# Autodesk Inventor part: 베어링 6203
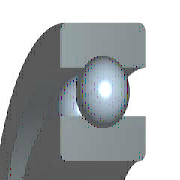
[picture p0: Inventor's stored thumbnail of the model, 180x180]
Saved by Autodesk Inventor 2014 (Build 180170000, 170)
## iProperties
IsCustomPart: 0
Created: 2009-02
Part Number: 베어링 6203
Material: 강, 연강
Description: 깊은 그루브 볼 베어링
Document SubType Name: Modeling
Standard: KS B 2023
Designer: 한국산업디자인학원 [http://gmhk.co.kr]
Standards Organization: KS
Language: ko-KR
Size Designation: 6203 - 17 x 40 x 12
Categories: <MemberInstance><Categories><Category DisplayName="샤프트 부품" InternalName="7f7aeb1f-a693-4053-b835-cee3144e0d98" Mnemonic="SHFT"><Category DisplayName="베어링" Inter
Density: 1 g/cm^3
Appearance: 크롬 - 광택
Author: pww
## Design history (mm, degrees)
sketch "스케치" dims "d0" = 5.98 (= -0.26 x WD + 0.26 x BD)
  geometry: L1 (3.01, 14.25)-(8.99, 14.25); L2 (6, 14.25)-(6, 11.26); L3 (6, 14.25)-(6, 17.24); L4 (3.778, 12.249)-(0, 12.249); L5 (0, 8.5)-(12, 8.5); L6 (3.778, 16.251)-(0, 16.251); L7 (0, 20)-(12, 20); L8 (12, 8.5)-(12, 12.249); L9 (8.222, 12.249)-(12, 12.249); L10 (8.222, 16.251)-(12, 16.251); L11 (12, 20)-(12, 16.251); L12 (-1.4, 0)-(8.4, 0) reference; L13 (0, -0.3)-(0, 5.3) reference
  constraints: 22 end point, 4 point on line, 2 collinear, 2 perpendicular, 2 symmetric about line, 1 midpoint, 1 parallel, 14 other
  dimensions: "d9" = 17 diameter of L5 L12 (= WD); "d11" = 40 diameter of L7 L12 (= BD); "d12" = 12 distance between parallel lines of L8 L13 (= KB); "d13" = 24.498 diameter of L9 L12 (= 0.326 x BD + 0.674 x WD)
revolve "본체" stored, may be unused: angle "d6" = 90 deg
revolve "볼" stored, may be unused: angle "d7" = 90 deg
pattern_circular "IDS_ARRAYBALL[SIMPL:T]" dims angle "d3" = 360 deg
body "Solid1"
fillet "모깎기1" dims "d1" = 0.6 (= KRS)
other parameters: "WD" = 17 [user parameter; used in 5 equation terms], "BD" = 40 [user parameter; used in 5 equation terms], "KB" = 12 [user parameter; used in 1 equation term], "KRS" = 0.6 [user parameter; used in 1 equation term], "d4" = 0, "d5" = 0, "d8" = 0, "d14" = 0, "d15" = 0, "BBA" = 0 [user parameter], "BC0" = 4750000 [user parameter], "BC" = 9560000 [user parameter], "WR" = 8.5 (= 0.5 x WD) [user parameter]
